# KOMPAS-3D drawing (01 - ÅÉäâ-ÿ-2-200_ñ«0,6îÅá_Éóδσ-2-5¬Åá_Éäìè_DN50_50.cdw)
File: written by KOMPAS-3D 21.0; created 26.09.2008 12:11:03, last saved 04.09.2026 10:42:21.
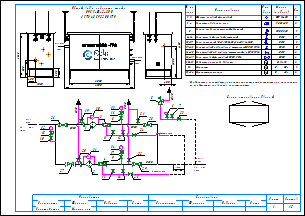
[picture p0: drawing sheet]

Sheets 1-2: A3, landscape

Document properties: Наименование: Макро:21; Автор: RaskoAdmin; Форматы листов документа: 2xA3; Полное имя файла: \\UR38nt01\Departments\КТО\КБ ПУРДГ\Заявки\Прайс-лист на типовые шкафы ГРПШ\ПРДГ_стандарт_20_03_2026\ПРДГ с РДНК\ПРДГ-Ш-2-200_до0,6МПа_Рвых-2-5кПа_РДНК_DN50_50.cdw

Title block, sheet 1: Наименование: Пункт учета газа / ПУГ-Ш-400-Р / ЛГТИ.485922.001ТУ; designation: ЛГТИ.03.4411141; sheet number: 1; Количество листов документа: 2; organisation: ООО "ЭЛЬСТЕР Газэлектроника"; Форматы листов документа: A3; stored path: C:\Рабочие документы\Компас\ПУГ\Схема.cdw; Разработал: Устинов; Проверил: Кошкин; Утвердил: Кошкин
Title block, sheet 2: sheet number: 2; stored path: D:\Рабочие документы\Заявки\ПУРДГ\ПУРДГ-ШУЭО-2-100-Р 4411220.cdw; designation, second copy: ЛГТИ.03.4411141-

Views: Вид 1, Вид 2
Referenced files: wcvoit.frw
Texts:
  Normal
  Вход
  газа
  PDI
  Выход
  Р=     кПа
  DN50
  DN20
  Импульс DN15
  ≥5DN
  HYSWLongFangSong
  № на
  схеме
  Усл.
  обозн.
  Марка
  (модель)
  Кол.
  Фильтр газовый фланцевый
  ФГ 16-50
  Регулятор давления газа
  РДНК-50
  Клапан предохранительный сбросной
  КПС DN20
  Кран шаровой газовый латунный
  DN15
  Кран кнопочный VE-РАСКО-НЗ-1,6-G1/2-М20
  Кран шаровой "под приварку" штуцерный DN20 PN16
  Кран шаровой "под приварку" штуцерный п/п DN15 PN16
  Кран шаровой фланцевый DN50 PN16
  Индикатор перепада давления
  Delta 15
  Манометр
  Манометр-напоромер
  0...     МПа
  0...     кПа
  Общий вид и габариты шкафа
  ПРДГ-Ш-2-200
  Выход газа
  Вход газа
  Схема открывания дверей
  Р=       МПа
  logo-rasko-ge.png
  Предприятие изготовитель может заменять комплектующие на аналогичные,
  не ухудшающие заявленных характеристик.
  Должность
  Конструктор
  Фамилия
  Подпись
  Дата
  Согласовано
  Максимкин
  Лист
  Листов
  POLYLINE_STYLE_0.18_RGB_0_0_0
  POLYLINE_STYLE_0.50_RGB_0_0_0
  POLYLINE_STYLE_0.34_RGB_0_0_0
  PHANTOM_RGB_0_0_0_SC_1_THICK_0.18
  K5LT_THIN_RGB_0_0_0_THICK_0.18
  K5LT32769_RGB_0_0_0_THICK_0.18
  K5LT12_RGB_0_0_0_SC_1_THICK_0.18
  K5LT_DASHED_RGB_0_0_0_SC_1_THICK_0.18
  ACISOTGL_RGB_0_0_0_SC_0.8_THICK_0.25
  CONTINUOUS_RGB_0_127_31_THICK_0.3
  CONTINUOUS_RGB_0_0_255_THICK_0.35
  CONTINUOUS_RGB_255_0_0_THICK_0.35
  POLYLINE_STYLE_0.25_RGB_0_0_0
  CONTINUOUS_RGB_0_0_0_THICK_0.5
  POLYLINE_STYLE_0.35_RGB_0_0_255
  CONTINUOUS_RGB_0_0_0_THICK_0.4
  CONTINUOUS_RGB_0_0_0_THICK_0.35
  Без оформления
Dimensions and other numbers on the sheet: 1; 2; 3; 4; 5; 10; 27; 28; 29; 23; 8; 12; 19; 20; 21; 22; 25; 24; 30; 31; 15; 16; 26; 6; 7; 11; 14; 13; 33; 1, 2; 3, 4; 6-14; 9; 15-17; 19-23; 24-25; 26-29; 30-31; 32; 33-34; 1000; 400; 1050; 500; 305; 2000; 4130; 1565; 2300; 17; 34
